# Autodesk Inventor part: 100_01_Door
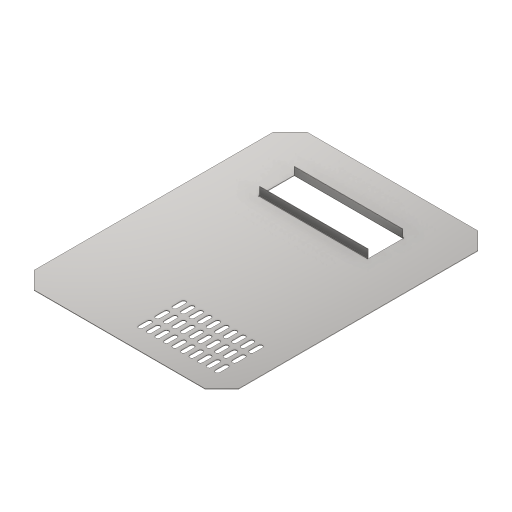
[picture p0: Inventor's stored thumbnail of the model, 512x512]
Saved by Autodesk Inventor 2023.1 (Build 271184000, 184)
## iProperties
Company: Fabian Stasiak CAD Consulting
Category: Autodesk® Inventor® Tutorial Series
Created: 2011-01
Part Number: 100_01_Door
Material: Steel
Document SubType Name: Konstrukcja blachowa
Designer: F.Stasiak
Density: 7.85 g/cm^3
Sheet Metal Rule: Steel 1.5 mm/Straight
Sheet Metal Width: 0,000 mm
Sheet Metal Length: 0,000 mm
Sheet Metal Area: 0,000 mm^2
Appearance: Stainless - Brushed
Catalog Web Link: www.expertbooks.eu
FLATAREA: =<FLAT PATTERN AREA>
Thickness: 1,500 mm
Author: F.Stasiak
Subject: Sheet Metal Design. Basic and Advanced techniques
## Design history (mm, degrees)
node "Powierzchnia1"
  sketch "Szkic1"
    geometry: L1 (-300, -350)-(-300, 350); L2 (-300, 350)-(-250, 400); L3 (-250, 400)-(250, 400); L4 (250, 400)-(300, 350); L5 (300, 350)-(300, -350); L6 (300, -350)-(250, -400); L7 (250, -400)-(-250, -400); L8 (-250, -400)-(-300, -350); L9 (0, 400)-(0, -400); L10 (-300, 0)-(300, 0); 2 further points
    constraints: 20 end point, 7 perpendicular, 5 midpoint, 2 vertical, 1 coincident, 1 parallel, 2 other
    dimensions: "d0" = 700 distance of L1.start L1.end; "d1" = 500 distance of L2.end L3.end; "d2" = 135 deg angle of L2 L1; "d3" = 800 distance between parallel lines of L7 L3
sketch "Szkic3"
  geometry: L1 (-250, 400)-(250, 400) reference; L2 (-160, 270)-(160, 270); L3 (160, 270)-(160, 170); L4 (160, 170)-(-160, 170); L5 (-160, 170)-(-160, 270); 2 further points
  constraints: 8 end point, 2 parallel, 1 horizontal, 1 midpoint, 1 perpendicular, 1 vertical alignment
  dimensions: "d19" = 320 distance of L3.end L4.end; "d20" = 100 distance of L2.end L3.end; "d21" = 130 distance between parallel lines of L1 L2
feature "Wytnij1" sketch "Szkic3" dims "d22" = 1.5 (= Thickness), "d23" = 0
node "Kołnierz1"
sketch "Szkic5"
  geometry: L1 (250, -400)-(-250, -400) reference; L2 (300, 350)-(300, -350) reference; 2 further points
  dimensions: "d34" = 75 distance from line of point (225, -325) L1; "d35" = 75 distance from line of L2 point (225, -325) (= d34)
feature "iFeature18:1" sketch "Szkic5"
feature "Ƅ耀ƃ耀ƀ耀ſ耀ž耀Ź耀Ÿ耀Ų耀" dims "d0" = 700, "d1" = 500, "d2" = 135 deg, "d3" = 800, "d4" = 1.5 (= BendRadius), "d19" = 320, "d20" = 100, "d21" = 130, "d22" = 1.5 (= Thickness), "d23" = 0, "d24" = 1.5 (= BendReliefWidth), "d25" = 0.75 (= BendReliefDepth), "d26" = 3 (= MinimumRemnant), "d27" = 1.5 (= BendRadius), "d28" = 25, "d29" = 90 deg, "d30" = 1.5 (= BendRadius), "d31" = 6 (= CornerReliefSize), "d32" = 1.5 (= GapSize), "d33" = 1.5 (= JacobiRadiusSize), "d34" = 75, "d35" = 75 (= d34), "d38" = 90 deg, "d39" = 100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
node "Bryła1"
pattern_linear "Szyk prostokątny1" dims "d41" = 25, "d44" = 50
feature "Płyta1" dims "d45" = 1.5 (= Thickness)
sketch "Szkic4"
  geometry: L1 (-318.5, 0)-(-1.5, 0); L2 (-1.5, 0)-(-1.5, 25); L3 (-1.5, 25)-(-318.5, 25); L4 (-318.5, 25)-(-318.5, 0)
  constraints: 8 end point
feature "Płyta3" dims "d24" = 1.5 (= BendReliefWidth), "d25" = 0.75 (= BendReliefDepth), "d26" = 3 (= MinimumRemnant), "d27" = 1.5 (= BendRadius), "d28" = 25, "d29" = 90 deg, "d30" = 1.5 (= BendRadius), "d31" = 6 (= CornerReliefSize), "d32" = 1.5 (= GapSize), "d33" = 1.5 (= JacobiRadiusSize), "d45" = 1.5 (= Thickness), "OdstępPołączenia" = 0.01
feature "Gięcie2" dims "d24" = 1.5 (= BendReliefWidth), "d25" = 0.75 (= BendReliefDepth), "d26" = 3 (= MinimumRemnant), "d27" = 1.5 (= BendRadius), "d28" = 25, "d29" = 90 deg, "d30" = 1.5 (= BendRadius), "d45" = 1.5 (= Thickness), "OdstępPołączenia" = 0.01
feature "Narożnik2" dims "d28" = 25, "d29" = 90 deg, "d31" = 6 (= CornerReliefSize), "d32" = 1.5 (= GapSize), "d33" = 1.5 (= JacobiRadiusSize)
